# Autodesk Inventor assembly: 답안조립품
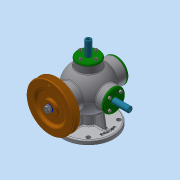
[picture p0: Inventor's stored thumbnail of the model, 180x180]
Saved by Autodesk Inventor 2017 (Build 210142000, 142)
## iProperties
Part Number: 답안조립품
Material: 일반
Document SubType Name: Assembly
Designer: MRC
Author: MRC
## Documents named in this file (17)
- C:\Users\MRC\Desktop\시험\600911V1004\답안조립품.iam
- C:\Users\MRC\Desktop\시험\600911V1004\본체.ipt
- C:\Users\MRC\Desktop\시험\600911V1004\V-벨트풀리.ipt
- C:\Users\MRC\Desktop\시험\600911V1004\너트 M8x1.ipt
- C:\Users\MRC\Desktop\시험\600911V1004\뒤커버.ipt
- C:\Users\MRC\Desktop\시험\600911V1004\베어링 6202.ipt
- C:\Users\MRC\Desktop\시험\600911V1004\본체커버.ipt
- C:\Users\MRC\Desktop\시험\600911V1004\볼트 M4.ipt
- C:\Users\MRC\Desktop\시험\600911V1004\스프링1.ipt
- C:\Users\MRC\Desktop\시험\600911V1004\스프링2.ipt
- C:\Users\MRC\Desktop\시험\600911V1004\슬라이드 커버.ipt
- C:\Users\MRC\Desktop\시험\600911V1004\슬라이드.ipt
- C:\Users\MRC\Desktop\시험\600911V1004\앞커버.ipt
- C:\Users\MRC\Desktop\시험\600911V1004\오일 실.ipt
- C:\Users\MRC\Desktop\시험\600911V1004\와셔 8x17.ipt
- C:\Users\MRC\Desktop\시험\600911V1004\축.ipt
- C:\Users\MRC\Desktop\시험\600911V1004\키 4x4.ipt
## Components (1 placed, 1 different names)
1. V-벨트풀리:1
